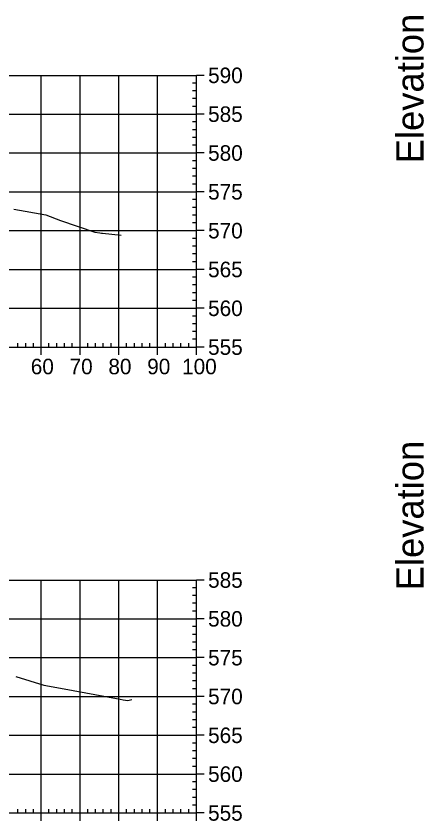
# Model space of a CAD drawing. Extents: x 708103 to 717568, y 374476 to 378707.
# Drawn here: x 711580.5 to 711685.6, y 377392.6 to 377599.9 of the extents above; entities that cross this region are included whole.
import ezdxf

# ---------------------------------------------------------------- set-up
doc = ezdxf.new("R2010")
doc.units = 0
for name, color, linetype in [('57', 7, 'Continuous'), ('60', 7, 'Continuous'), ('Existing', 7, 'Continuous')]:
    doc.layers.add(name, color=color, linetype=linetype)

msp = doc.modelspace()

# ---------------------------------------------------------------- linework, layer by layer
at = {"layer": '57'}
for p, q in [((711426.98, 377584.63), (711626.98, 377584.63)), ((711586.98, 377514.63), (711586.98, 377584.63)), ((711596.98, 377514.63), (711596.98, 377584.63)), ((711606.98, 377514.63), (711606.98, 377584.63)), ((711616.98, 377514.63), (711616.98, 377584.63)), ((711626.98, 377514.63), (711626.98, 377584.63)), ((711626.98, 377514.63), (711626.98, 377584.63)), ((711628.98, 377584.63), (711626.98, 377584.63)), ((711626.98, 377582.63), (711625.98, 377582.63)), ((711626.98, 377580.63), (711625.98, 377580.63)), ((711626.98, 377578.63), (711625.98, 377578.63)), ((711626.98, 377576.63), (711625.98, 377576.63)), ((711426.98, 377574.63), (711626.98, 377574.63)), ((711628.98, 377574.63), (711626.98, 377574.63)), ((711626.98, 377572.63), (711625.98, 377572.63)), ((711626.98, 377570.63), (711625.98, 377570.63)), ((711626.98, 377568.63), (711625.98, 377568.63)), ((711626.98, 377566.63), (711625.98, 377566.63)), ((711426.98, 377564.63), (711626.98, 377564.63)), ((711628.98, 377564.63), (711626.98, 377564.63)), ((711626.98, 377562.63), (711625.98, 377562.63)), ((711626.98, 377560.63), (711625.98, 377560.63)), ((711626.98, 377558.63), (711625.98, 377558.63)), ((711626.98, 377556.63), (711625.98, 377556.63)), ((711426.98, 377554.63), (711626.98, 377554.63)), ((711628.98, 377554.63), (711626.98, 377554.63)), ((711626.98, 377552.63), (711625.98, 377552.63)), ((711626.98, 377550.63), (711625.98, 377550.63)), ((711626.98, 377548.63), (711625.98, 377548.63)), ((711626.98, 377546.63), (711625.98, 377546.63)), ((711426.98, 377544.63), (711626.98, 377544.63)), ((711628.98, 377544.63), (711626.98, 377544.63)), ((711626.98, 377542.63), (711625.98, 377542.63)), ((711626.98, 377540.63), (711625.98, 377540.63)), ((711626.98, 377538.63), (711625.98, 377538.63)), ((711626.98, 377536.63), (711625.98, 377536.63)), ((711426.98, 377534.63), (711626.98, 377534.63)), ((711628.98, 377534.63), (711626.98, 377534.63)), ((711626.98, 377532.63), (711625.98, 377532.63)), ((711626.98, 377530.63), (711625.98, 377530.63)), ((711626.98, 377528.63), (711625.98, 377528.63)), ((711626.98, 377526.63), (711625.98, 377526.63)), ((711426.98, 377524.63), (711626.98, 377524.63)), ((711628.98, 377524.63), (711626.98, 377524.63)), ((711626.98, 377522.63), (711625.98, 377522.63)), ((711626.98, 377520.63), (711625.98, 377520.63)), ((711626.98, 377518.63), (711625.98, 377518.63)), ((711426.98, 377514.63), (711626.98, 377514.63)), ((711426.98, 377514.63), (711626.98, 377514.63)), ((711580.98, 377514.63), (711580.98, 377515.63)), ((711582.98, 377514.63), (711582.98, 377515.63)), ((711584.98, 377514.63), (711584.98, 377515.63)), ((711586.98, 377512.63), (711586.98, 377514.63)), ((711588.98, 377514.63), (711588.98, 377515.63)), ((711590.98, 377514.63), (711590.98, 377515.63)), ((711592.98, 377514.63), (711592.98, 377515.63)), ((711594.98, 377514.63), (711594.98, 377515.63)), ((711596.98, 377512.63), (711596.98, 377514.63)), ((711598.98, 377514.63), (711598.98, 377515.63)), ((711600.98, 377514.63), (711600.98, 377515.63)), ((711602.98, 377514.63), (711602.98, 377515.63)), ((711604.98, 377514.63), (711604.98, 377515.63)), ((711606.98, 377512.63), (711606.98, 377514.63)), ((711608.98, 377514.63), (711608.98, 377515.63)), ((711610.98, 377514.63), (711610.98, 377515.63)), ((711612.98, 377514.63), (711612.98, 377515.63)), ((711614.98, 377514.63), (711614.98, 377515.63)), ((711616.98, 377512.63), (711616.98, 377514.63)), ((711618.98, 377514.63), (711618.98, 377515.63)), ((711620.98, 377514.63), (711620.98, 377515.63)), ((711622.98, 377514.63), (711622.98, 377515.63)), ((711624.98, 377514.63), (711624.98, 377515.63)), ((711626.98, 377516.63), (711625.98, 377516.63)), ((711626.98, 377512.63), (711626.98, 377514.63)), ((711628.98, 377514.63), (711626.98, 377514.63)), ((711426.98, 377454.63), (711626.98, 377454.63)), ((711586.98, 377394.63), (711586.98, 377454.63)), ((711596.98, 377394.63), (711596.98, 377454.63)), ((711606.98, 377394.63), (711606.98, 377454.63)), ((711616.98, 377394.63), (711616.98, 377454.63)), ((711626.98, 377394.63), (711626.98, 377454.63)), ((711626.98, 377394.63), (711626.98, 377454.63)), ((711628.98, 377454.63), (711626.98, 377454.63)), ((711626.98, 377452.63), (711625.98, 377452.63)), ((711626.98, 377450.63), (711625.98, 377450.63)), ((711626.98, 377448.63), (711625.98, 377448.63)), ((711626.98, 377446.63), (711625.98, 377446.63)), ((711426.98, 377444.63), (711626.98, 377444.63)), ((711628.98, 377444.63), (711626.98, 377444.63)), ((711626.98, 377442.63), (711625.98, 377442.63)), ((711626.98, 377440.63), (711625.98, 377440.63)), ((711626.98, 377438.63), (711625.98, 377438.63)), ((711626.98, 377436.63), (711625.98, 377436.63)), ((711426.98, 377434.63), (711626.98, 377434.63)), ((711628.98, 377434.63), (711626.98, 377434.63)), ((711626.98, 377432.63), (711625.98, 377432.63)), ((711626.98, 377430.63), (711625.98, 377430.63)), ((711626.98, 377428.63), (711625.98, 377428.63)), ((711626.98, 377426.63), (711625.98, 377426.63)), ((711426.98, 377424.63), (711626.98, 377424.63)), ((711628.98, 377424.63), (711626.98, 377424.63)), ((711626.98, 377422.63), (711625.98, 377422.63)), ((711626.98, 377420.63), (711625.98, 377420.63)), ((711626.98, 377418.63), (711625.98, 377418.63)), ((711626.98, 377416.63), (711625.98, 377416.63)), ((711426.98, 377414.63), (711626.98, 377414.63)), ((711628.98, 377414.63), (711626.98, 377414.63)), ((711626.98, 377412.63), (711625.98, 377412.63)), ((711626.98, 377410.63), (711625.98, 377410.63)), ((711626.98, 377408.63), (711625.98, 377408.63)), ((711626.98, 377406.63), (711625.98, 377406.63)), ((711426.98, 377404.63), (711626.98, 377404.63)), ((711628.98, 377404.63), (711626.98, 377404.63)), ((711626.98, 377402.63), (711625.98, 377402.63)), ((711626.98, 377400.63), (711625.98, 377400.63)), ((711626.98, 377398.63), (711625.98, 377398.63)), ((711626.98, 377396.63), (711625.98, 377396.63)), ((711426.98, 377394.63), (711626.98, 377394.63)), ((711426.98, 377394.63), (711626.98, 377394.63)), ((711580.98, 377394.63), (711580.98, 377395.63)), ((711582.98, 377394.63), (711582.98, 377395.63)), ((711584.98, 377394.63), (711584.98, 377395.63)), ((711586.98, 377392.63), (711586.98, 377394.63)), ((711588.98, 377394.63), (711588.98, 377395.63)), ((711590.98, 377394.63), (711590.98, 377395.63)), ((711592.98, 377394.63), (711592.98, 377395.63)), ((711594.98, 377394.63), (711594.98, 377395.63)), ((711596.98, 377392.63), (711596.98, 377394.63)), ((711598.98, 377394.63), (711598.98, 377395.63)), ((711600.98, 377394.63), (711600.98, 377395.63)), ((711602.98, 377394.63), (711602.98, 377395.63)), ((711604.98, 377394.63), (711604.98, 377395.63)), ((711606.98, 377392.63), (711606.98, 377394.63)), ((711608.98, 377394.63), (711608.98, 377395.63)), ((711610.98, 377394.63), (711610.98, 377395.63)), ((711612.98, 377394.63), (711612.98, 377395.63)), ((711614.98, 377394.63), (711614.98, 377395.63)), ((711616.98, 377392.63), (711616.98, 377394.63)), ((711618.98, 377394.63), (711618.98, 377395.63)), ((711620.98, 377394.63), (711620.98, 377395.63)), ((711622.98, 377394.63), (711622.98, 377395.63)), ((711624.98, 377394.63), (711624.98, 377395.63)), ((711626.98, 377392.63), (711626.98, 377394.63)), ((711628.98, 377394.63), (711626.98, 377394.63))]:
    msp.add_line(p, q, dxfattribs=at)
at = {"layer": 'Existing'}
for points in [[(711579.9, 377550.13), (711588.18, 377548.68), (711591.96, 377547.26), (711600.83, 377544.2), (711602.1, 377544.02), (711602.51, 377543.97), (711602.77, 377543.98), (711607.56, 377543.5)], [(711580.43, 377429.8), (711587.67, 377427.56), (711591.96, 377426.79), (711607.33, 377423.94), (711608.12, 377423.76), (711609.28, 377423.62), (711610.36, 377423.87)]]:
    msp.add_lwpolyline(points, dxfattribs=at)

# ---------------------------------------------------------------- texts
at = {"layer": '57'}
for s, p in [('590', (711629.98, 377582.63)), ('585', (711629.98, 377572.63)), ('580', (711629.98, 377562.63)), ('575', (711629.98, 377552.63)), ('570', (711629.98, 377542.63)), ('565', (711629.98, 377532.63)), ('560', (711629.98, 377522.63)), ('555', (711629.98, 377512.63)), ('60', (711584.29, 377507.63)), ('70', (711594.29, 377507.63)), ('80', (711604.29, 377507.63)), ('90', (711614.29, 377507.63)), ('100', (711623.28, 377507.63)), ('585', (711629.98, 377452.63)), ('580', (711629.98, 377442.63)), ('575', (711629.98, 377432.63)), ('570', (711629.98, 377422.63)), ('565', (711629.98, 377412.63)), ('560', (711629.98, 377402.63)), ('555', (711629.98, 377392.63))]:
    msp.add_text(s, height=4, dxfattribs=at).set_placement(p)
at = {"layer": '60'}
for p in [(711685.48, 377561.99), (711685.48, 377451.99)]:
    msp.add_text('Elevation', height=7, rotation=90, dxfattribs=at).set_placement(p)

doc.saveas('drawing.dxf')
